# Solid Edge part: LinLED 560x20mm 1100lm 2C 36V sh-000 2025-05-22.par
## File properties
Author: jaroslaw.przewlocki
Template: iso metric part.par
Last saved by: jaroslaw.przewlocki
Revision: 3
Application: Solid Edge
Gęstość: 0,000 kg/m^3
Dokładność: 0,990
Username: jaroslaw.przewlocki
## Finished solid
Body 1: solid body, 1157 faces, 3004 edges, 1941 vertices.
  Faces by surface: plane 824, cylinder 170, torus 68, cone 50, spline 24, sphere 21
  Edges by curve: line 2308, curve on surface 360, circle 231, ellipse 71, spline 34
Bounding box of the edges (mm; curved faces can reach further): 559.600 x 20.000 x 4.450, from (-279.8, -10, -1) to (279.8, 10, 3.45).
Cylindrical faces by radius (mm): R0.1 x6, R0.2 x46, R0.2169 x6, R0.25 x32, R0.3373 x6, R0.4 x8, R0.4006 x2, R0.4008 x2, R0.525 x2, R0.6 x20, R1 x12, R1.1 x4, R1.1989 x2, R1.199 x2, R1.2 x10, R2.15 x10
Conical faces (half-angle, radius in mm at the cone's reference point): 0.398 deg R1.1964 x2, 0.4493 deg R1.1964 x2, 0.4746 deg R1.1948 x2, 0.4758 deg R1.1948 x2, 0.5 deg R0.5056 x4, 0.5 deg R1.0082 x4, 1 deg R0.5511 x2, 10 deg R0.2132 x4, 10 deg R0.4132 x4, 16.0099 deg R1.1053 x2, 16.1249 deg R1.1279 x2, 18.8604 deg R1.0669 x4, 19.5041 deg R0.5138 x2, 19.8244 deg R0.5099 x2, 27.363 deg R0.6214 x2, 40.6434 deg R0.5161 x2, 43.3309 deg R0.4892 x2, 45 deg R0.575 x2, 45 deg R0.625 x4
Toroidal faces (ring radius, tube radius in mm): R0.0958 r0.3997 x4, R0.1076 r0.4 x2, R0.1101 r0.4001 x2, R0.1217 r0.4 x2, R0.1234 r0.4 x2, R0.1626 r0.228 x2, R0.1634 r0.2287 x2, R0.3287 r0.2001 x2, R0.3322 r0.2 x2, R0.3684 r0.2151 x2, R0.3703 r0.4 x2, R0.3818 r0.2 x4, R0.4166 r0.3983 x2, R0.5981 r0.197 x2, R0.5982 r0.197 x2, R0.6009 r0.3968 x2, R0.6009 r0.3969 x2, R0.6227 r0.2 x2, R0.6235 r0.2 x2, R0.8 r0.2 x4, R0.8522 r0.3 x2, R0.9002 r0.2 x2, R0.9018 r0.2 x2, R0.9197 r0.223 x2, R0.9365 r0.2 x2, R0.9663 r0.2263 x2, R0.9665 r0.2263 x2, R1.2 r0.1 x2, R1.429 r1.2 x2, R1.8741 r0.2175 x2, R1.9007 r0.2 x2
Spherical faces by radius (mm): R0.1 x5, R0.2 x12, R0.6 x4
Planar faces by outward normal: +x 98, +y 103, +z 135, -x 98, -y 105, -z 9, oblique 276
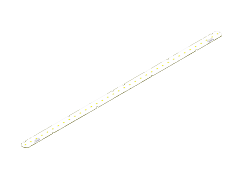
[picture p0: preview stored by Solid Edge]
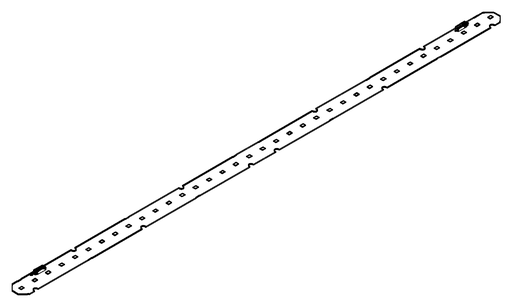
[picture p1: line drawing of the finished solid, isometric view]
